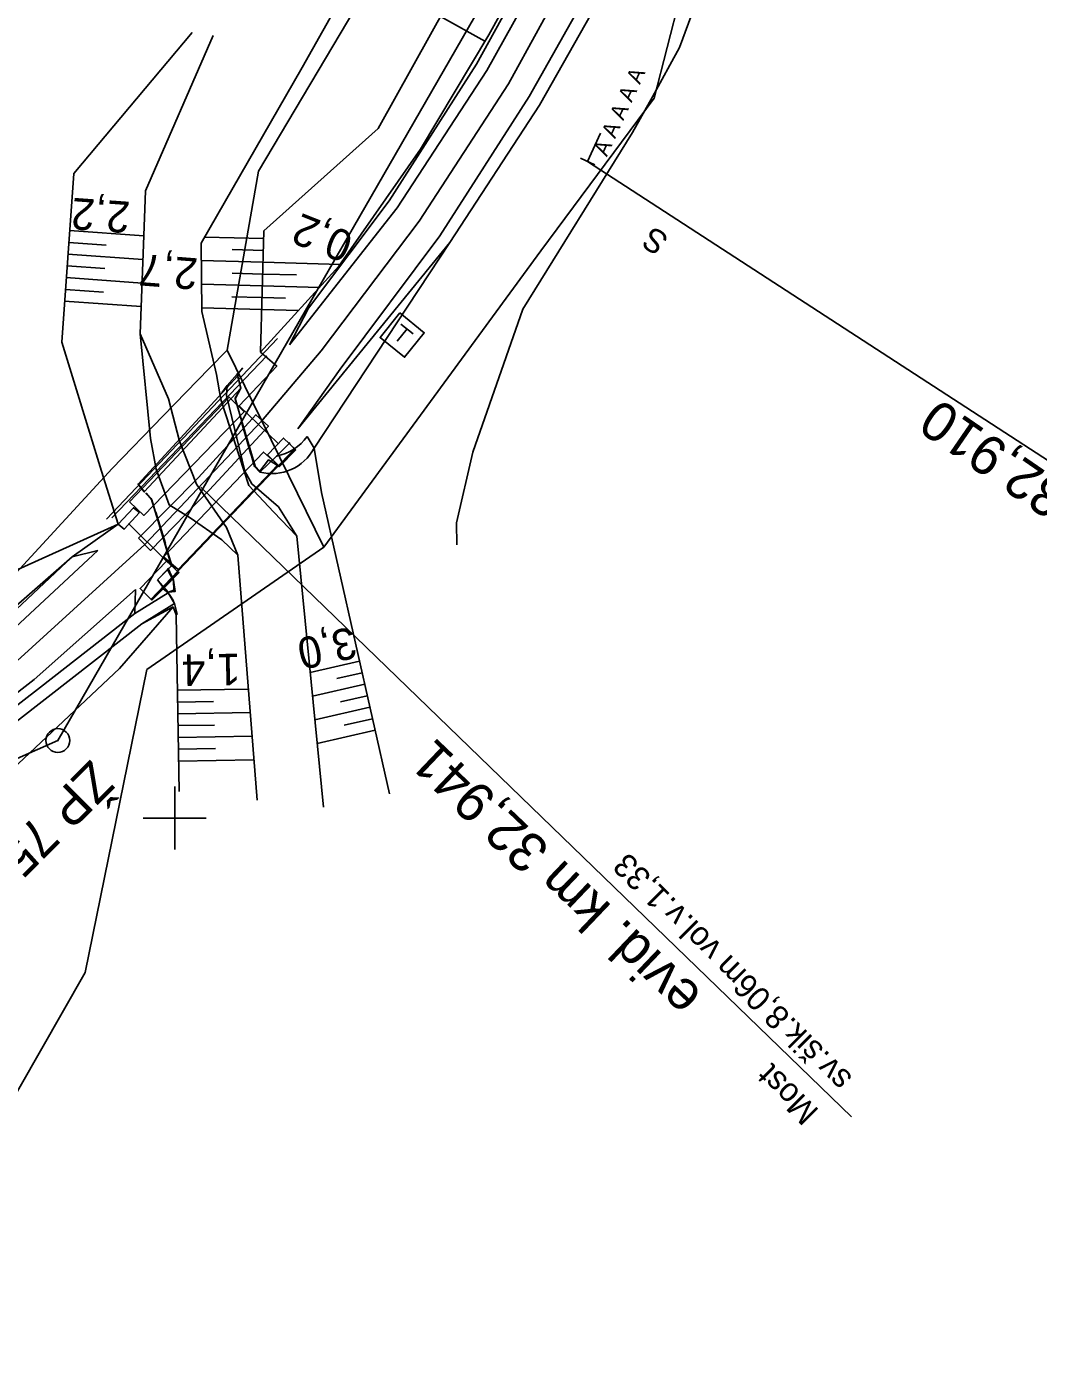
# Model space of a CAD drawing. Extents: x -804166 to -803706, y -1151030 to -1150147.
# Drawn here: x -803909.4 to -803845.1, y -1150734.2 to -1150649.7 of the extents above; entities that cross this region are included whole.
import ezdxf

# ---------------------------------------------------------------- set-up
doc = ezdxf.new("R2010")
doc.units = 0
for name, color, linetype in [('0381KM032-037P - Vrstva 1', 7, 'Continuous'), ('0381KM032-037P - Vrstva 13', 7, 'Continuous'), ('0381KM032-037P - Vrstva 17', 7, 'Continuous'), ('0381KM032-037P - Vrstva 18', 7, 'Continuous'), ('0381KM032-037P - Vrstva 33', 7, 'Continuous'), ('0381KM032-037P - Vrstva 35', 7, 'Continuous'), ('0381KM032-037P - Vrstva 4', 7, 'Continuous'), ('0381KM032-037P - Vrstva 48', 7, 'Continuous'), ('0381KM032-037P - Vrstva 49', 7, 'Continuous'), ('0381KM032-037P - Vrstva 50', 7, 'Continuous'), ('0381KM032-037P - Vrstva 55', 7, 'Continuous'), ('0381KM032-037P - Vrstva 6', 7, 'Continuous'), ('hran DP - hran DP', 7, 'Continuous'), ('krizky_1000 - Vrstva 1', 7, 'Continuous'), ('vyt_sit - polygon', 7, 'Continuous'), ('vyt_sit - stávající', 7, 'Continuous')]:
    doc.layers.add(name, color=color, linetype=linetype)

msp = doc.modelspace()

# ---------------------------------------------------------------- linework, layer by layer
at = {"layer": '0381KM032-037P - Vrstva 1'}
msp.add_line((-803894.474, -1150674.768), (-803901.906, -1150682.605), dxfattribs=at)
for points in [[(-803862.645, -1150536.71), (-803860.057, -1150547.81), (-803858.364, -1150558.718), (-803857.51, -1150569.546), (-803857.425, -1150579.975), (-803858.096, -1150590.725), (-803859.58, -1150601.687), (-803861.73, -1150611.946), (-803864.691, -1150622.329), (-803868.306, -1150632.261), (-803873.118, -1150643.006), (-803878.784, -1150653.323), (-803884.455, -1150662.043), (-803890.68, -1150670.289), (-803894.474, -1150674.768)], [(-803901.906, -1150682.605), (-803910.014, -1150690), (-803918.643, -1150696.775), (-803928.041, -1150703.062), (-803937.946, -1150708.688), (-803946.795, -1150712.932), (-803956.655, -1150716.869), (-803966.853, -1150720.098), (-803973.694, -1150721.813), (-803983.505, -1150723.682), (-803993.918, -1150724.91), (-804004.459, -1150725.421), (-804014.948, -1150725.206), (-804025.475, -1150724.252), (-804035.41, -1150722.673), (-804044.081, -1150720.735), (-804054.774, -1150717.615), (-804061.472, -1150715.138)]]:
    msp.add_lwpolyline(points, dxfattribs=at)
at = {"layer": '0381KM032-037P - Vrstva 13'}
for p, q in [((-803900.427, -1150685.689), (-803900.743, -1150685.422)), ((-803900.427, -1150685.69), (-803902.54, -1150686.99)), ((-803900.02, -1150686.371), (-803900.089, -1150686.205)), ((-803900.019, -1150686.37), (-803902.092, -1150687.65))]:
    msp.add_line(p, q, dxfattribs=at)
for points in [[(-803900.743, -1150685.422), (-803900.692, -1150685.394), (-803900.742, -1150685.419)], [(-803900.02, -1150686.371), (-803899.851, -1150687.044), (-803899.848, -1150687.042), (-803900.019, -1150686.37), (-803900.427, -1150685.69), (-803900.742, -1150685.419)], [(-803900.089, -1150686.205), (-803900.081, -1150686.195), (-803900.317, -1150685.837), (-803900.317, -1150685.836), (-803900.427, -1150685.689)], [(-803902.54, -1150686.99), (-803908.533, -1150691.682), (-803917.537, -1150698.646), (-803926.885, -1150705.063), (-803937.003, -1150710.487), (-803946.017, -1150714.661), (-803956.263, -1150718.85), (-803966.288, -1150722.189), (-803972.538, -1150724.259)], [(-803972.286, -1150725.012), (-803966.125, -1150722.974), (-803955.955, -1150719.581), (-803945.709, -1150715.376), (-803936.565, -1150711.19), (-803926.506, -1150705.78), (-803917.073, -1150699.315), (-803908.044, -1150692.29), (-803902.092, -1150687.65)]]:
    msp.add_lwpolyline(points, dxfattribs=at)
at = {"layer": '0381KM032-037P - Vrstva 17'}
for p, q in [((-803903.995, -1150680.91), (-803894.145, -1150670.618)), ((-803892.37, -1150676.505), (-803901.521, -1150686.105))]:
    msp.add_line(p, q, dxfattribs=at)
for points in [[(-803867.911, -1150651.01), (-803864.194, -1150640.965), (-803863.34, -1150639.848), (-803860.107, -1150635.351), (-803857.384, -1150629.008), (-803845.634, -1150598.77), (-803839.769, -1150573.178), (-803837.289, -1150572.72)], [(-803882.068, -1150682.623), (-803882.094, -1150681.238), (-803881.038, -1150676.732), (-803877.877, -1150667.643), (-803870.889, -1150656.426), (-803869.632, -1150654.159), (-803867.911, -1150651.01)]]:
    msp.add_lwpolyline(points, dxfattribs=at)
at = {"layer": '0381KM032-037P - Vrstva 18'}
for p, q in [((-803902.321, -1150678.769), (-803895.977, -1150671.88)), ((-803895.96, -1150671.875), (-803897.006, -1150672.976)), ((-803895.972, -1150671.746), (-803896.032, -1150671.776)), ((-803895.788, -1150672.67), (-803901.935, -1150679.269)), ((-803896.656, -1150672.511), (-803897.006, -1150672.976)), ((-803895.788, -1150672.67), (-803895.788, -1150672.67)), ((-803895.902, -1150673.797), (-803893.451, -1150676.167)), ((-803895.155, -1150676.86), (-803895.737, -1150674.89)), ((-803892.742, -1150676.15), (-803892.333, -1150676.585)), ((-803891.585, -1150675.741), (-803891.14, -1150676.484)), ((-803893.531, -1150676.988), (-803894.581, -1150678.003)), ((-803892.333, -1150676.585), (-803893.36, -1150677.66)), ((-803892.31, -1150676.591), (-803892.333, -1150676.585)), ((-803893.36, -1150677.66), (-803893.335, -1150677.645)), ((-803901.935, -1150679.269), (-803902.321, -1150678.769)), ((-803856.973, -1150719.009), (-803898.348, -1150678.956)), ((-803900.514, -1150683.661), (-803902.936, -1150681.284)), ((-803900.594, -1150682.547), (-803901.206, -1150680.55)), ((-803900.177, -1150683.94), (-803901.093, -1150684.85)), ((-803900.181, -1150683.948), (-803900.177, -1150683.94)), ((-803899.733, -1150684.407), (-803899.765, -1150684.362)), ((-803900.692, -1150685.394), (-803901.461, -1150686.142)), ((-803900.692, -1150685.394), (-803901.093, -1150684.85)), ((-803900.087, -1150684.927), (-803900.086, -1150684.886)), ((-803900.387, -1150685.649), (-803899.968, -1150685.591))]:
    msp.add_line(p, q, dxfattribs=at)
for points in [[(-803895.902, -1150673.797), (-803893.509, -1150671.262), (-803894.538, -1150670.386)], [(-803892.244, -1150682.081), (-803893.405, -1150680.212), (-803895.1, -1150678.76), (-803895.543, -1150677.939), (-803896.702, -1150673.136), (-803896.656, -1150672.511), (-803896.032, -1150671.776)], [(-803894.595, -1150677.949), (-803894.892, -1150677.628), (-803896.154, -1150673.353), (-803896.156, -1150673.313), (-803895.788, -1150672.67), (-803896.032, -1150671.776), (-803895.682, -1150671.402), (-803895.972, -1150671.746), (-803895.977, -1150671.88)], [(-803896.154, -1150673.353), (-803895.788, -1150672.67), (-803895.977, -1150671.88)], [(-803895.96, -1150671.875), (-803896.006, -1150671.732), (-803896.032, -1150671.776)], [(-803902.876, -1150679.904), (-803896.545, -1150673.237), (-803895.586, -1150674.167), (-803901.958, -1150680.766), (-803902.876, -1150679.904)], [(-803896.156, -1150673.313), (-803894.92, -1150677.658), (-803894.581, -1150678.003)], [(-803902.301, -1150682.211), (-803901.541, -1150682.984), (-803897.786, -1150679.126), (-803894.042, -1150675.093), (-803894.835, -1150674.357), (-803898.482, -1150678.342), (-803902.301, -1150682.211)], [(-803892.31, -1150676.591), (-803893.094, -1150675.842), (-803894.104, -1150676.91), (-803893.335, -1150677.645), (-803892.31, -1150676.591)], [(-803892.742, -1150676.15), (-803892.697, -1150676.16), (-803893.531, -1150676.988)], [(-803900.704, -1150683.386), (-803899.78, -1150684.198), (-803893.446, -1150677.55), (-803894.353, -1150676.739), (-803900.704, -1150683.386)], [(-803894.581, -1150678.003), (-803894.595, -1150677.949), (-803894.041, -1150677.229), (-803894.041, -1150677.229), (-803893.36, -1150677.66)], [(-803901.935, -1150679.269), (-803901.931, -1150679.271), (-803902.334, -1150678.769), (-803902.321, -1150678.769)], [(-803900.181, -1150683.948), (-803901.502, -1150679.684), (-803901.835, -1150679.365), (-803901.815, -1150679.357), (-803901.461, -1150679.762), (-803900.212, -1150683.983), (-803900.181, -1150683.948)], [(-803902.232, -1150680.579), (-803903.222, -1150681.645), (-803903.605, -1150681.318), (-803902.621, -1150680.279), (-803902.232, -1150680.579)], [(-803899.765, -1150684.362), (-803901.461, -1150686.142), (-803902.204, -1150685.415), (-803900.514, -1150683.661), (-803899.765, -1150684.362)], [(-803901.093, -1150684.85), (-803901.09, -1150684.852), (-803900.467, -1150684.209), (-803900.408, -1150684.126), (-803900.086, -1150684.886), (-803899.968, -1150685.591), (-803900.061, -1150685.507), (-803900.087, -1150684.927), (-803900.467, -1150684.209)], [(-803900.177, -1150683.94), (-803899.733, -1150684.407), (-803900.692, -1150685.394)], [(-803901.09, -1150684.852), (-803900.387, -1150685.649), (-803900.061, -1150685.507)]]:
    msp.add_lwpolyline(points, dxfattribs=at)
for centre, major_axis, ratio, start_param, end_param in [((-803893.838, -1150674.452), (2.475, 1.269), 0.908828, 4.38934, 5.247205), ((-803893.887, -1150674.932), (1.395, -2.862), 0.971802, 5.593201, 6.899505)]:
    msp.add_ellipse(centre, major_axis=major_axis, ratio=ratio, start_param=start_param, end_param=end_param, dxfattribs=at)
at = {"layer": '0381KM032-037P - Vrstva 33'}
for p, q in [((-803885.617, -1150668.595), (-803884.838, -1150669.222)), ((-803885.227, -1150668.909), (-803885.855, -1150669.687))]:
    msp.add_line(p, q, dxfattribs=at)
msp.add_lwpolyline([(-803885.693, -1150667.892), (-803884.135, -1150669.146), (-803885.389, -1150670.704), (-803886.947, -1150669.45), (-803885.693, -1150667.892)], dxfattribs=at)
at = {"layer": '0381KM032-037P - Vrstva 35'}
msp.add_line((-803904.333, -1150681.001), (-803893.471, -1150669.506), dxfattribs=at)
at = {"layer": '0381KM032-037P - Vrstva 4'}
for points in [[(-803862.041, -1150601.171), (-803863.934, -1150611.478), (-803866.955, -1150621.666), (-803870.636, -1150631.623), (-803875.322, -1150642.112), (-803880.813, -1150652.073), (-803886.36, -1150660.761), (-803891.5, -1150667.581), (-803892.695, -1150669.921)], [(-803861.107, -1150601.386), (-803863.249, -1150611.592), (-803866.278, -1150621.841), (-803869.683, -1150631.826), (-803874.548, -1150642.393), (-803880.159, -1150652.477), (-803885.847, -1150661.208), (-803892.695, -1150669.921)], [(-803858.016, -1150602.009), (-803860.157, -1150612.315), (-803863.229, -1150623.106), (-803866.722, -1150632.775), (-803871.621, -1150643.742), (-803877.472, -1150654.13), (-803883.137, -1150662.978), (-803889.477, -1150671.458), (-803892.178, -1150675.246)], [(-803857.109, -1150602.102), (-803859.611, -1150612.518), (-803862.49, -1150623.34), (-803866.1, -1150633.182), (-803870.873, -1150644.181), (-803876.806, -1150654.687), (-803882.51, -1150663.405), (-803892.178, -1150675.246)], [(-803904.886, -1150683.001), (-803906.516, -1150683.391), (-803911.518, -1150688.069), (-803920.109, -1150694.835), (-803929.412, -1150700.935), (-803939.155, -1150706.209), (-803947.889, -1150710.398), (-803957.601, -1150714.533), (-803967.413, -1150717.637)], [(-803904.886, -1150683.001), (-803911.05, -1150688.735), (-803919.705, -1150695.384), (-803929.087, -1150701.477), (-803938.787, -1150707.105), (-803947.481, -1150711.337), (-803957.418, -1150715.321), (-803967.176, -1150718.433)], [(-803902.503, -1150685.469), (-803908.943, -1150691.185), (-803917.694, -1150697.991), (-803927.241, -1150704.348), (-803937.195, -1150710.055), (-803946.246, -1150714.302), (-803956.405, -1150718.419), (-803966.448, -1150721.526)], [(-803902.503, -1150685.469), (-803902.54, -1150686.99), (-803908.533, -1150691.682), (-803917.537, -1150698.646), (-803926.885, -1150705.063), (-803937.003, -1150710.487), (-803946.017, -1150714.661), (-803956.263, -1150718.85), (-803966.288, -1150722.189)]]:
    msp.add_lwpolyline(points, dxfattribs=at)
at = {"layer": '0381KM032-037P - Vrstva 48'}
for p, q in [((-803883.093, -1150649.037), (-803880.278, -1150650.604)), ((-803906.68, -1150662.653), (-803901.962, -1150662.988)), ((-803906.733, -1150663.401), (-803904.362, -1150663.569)), ((-803894.338, -1150663.165), (-803898.097, -1150663.061)), ((-803906.786, -1150664.149), (-803902.02, -1150664.487)), ((-803894.358, -1150663.915), (-803896.337, -1150663.86)), ((-803906.84, -1150664.897), (-803904.445, -1150665.067)), ((-803894.379, -1150664.664), (-803898.309, -1150664.555)), ((-803894.379, -1150664.664), (-803889.482, -1150664.8)), ((-803906.893, -1150665.645), (-803902.079, -1150665.987)), ((-803894.421, -1150666.164), (-803898.295, -1150666.056)), ((-803894.4, -1150665.414), (-803896.351, -1150665.36)), ((-803894.4, -1150665.414), (-803892.261, -1150665.473)), ((-803906.946, -1150666.394), (-803904.527, -1150666.565)), ((-803894.442, -1150666.913), (-803896.365, -1150666.86)), ((-803894.442, -1150666.913), (-803892.948, -1150666.955)), ((-803894.421, -1150666.164), (-803890.788, -1150666.265)), ((-803906.999, -1150667.142), (-803902.138, -1150667.487)), ((-803894.462, -1150667.663), (-803898.28, -1150667.557)), ((-803894.462, -1150667.663), (-803892.12, -1150667.728)), ((-803888.25, -1150690.03), (-803891.388, -1150690.739)), ((-803888.085, -1150690.761), (-803889.7, -1150691.126)), ((-803899.836, -1150691.878), (-803895.322, -1150691.802)), ((-803887.92, -1150691.493), (-803891.24, -1150692.243)), ((-803887.754, -1150692.224), (-803889.46, -1150692.61)), ((-803899.823, -1150692.628), (-803897.543, -1150692.589)), ((-803887.589, -1150692.956), (-803891.092, -1150693.748)), ((-803899.81, -1150693.378), (-803895.204, -1150693.3)), ((-803887.424, -1150693.688), (-803889.221, -1150694.094)), ((-803899.798, -1150694.128), (-803897.472, -1150694.088)), ((-803899.785, -1150694.878), (-803895.086, -1150694.798)), ((-803887.258, -1150694.419), (-803890.945, -1150695.252)), ((-803899.772, -1150695.628), (-803897.4, -1150695.587)), ((-803899.76, -1150696.377), (-803894.968, -1150696.296))]:
    msp.add_line(p, q, dxfattribs=at)
at = {"layer": '0381KM032-037P - Vrstva 49'}
for p, q in [((-803882.51, -1150663.405), (-803891.14, -1150676.484)), ((-803900.099, -1150686.57), (-803902.092, -1150687.65))]:
    msp.add_line(p, q, dxfattribs=at)
for points in [[(-803855.009, -1150569.422), (-803855.013, -1150580.14), (-803855.681, -1150591.137), (-803857.109, -1150602.102), (-803859.611, -1150612.518), (-803862.49, -1150623.34), (-803866.1, -1150633.182), (-803870.873, -1150644.181), (-803876.806, -1150654.687), (-803882.51, -1150663.405)], [(-803867.826, -1150615.469), (-803873.958, -1150632.621), (-803887.064, -1150656.172), (-803894.324, -1150662.675), (-803894.538, -1150670.386)], [(-803865.684, -1150616.069), (-803868.473, -1150625.045), (-803871.506, -1150633.468), (-803875.458, -1150641.91), (-803880.036, -1150650.199), (-803884.384, -1150657.469), (-803889.567, -1150664.922), (-803894.538, -1150670.386)], [(-803879.144, -1150629.624), (-803891.889, -1150652.288), (-803898.32, -1150663.448), (-803898.278, -1150667.796), (-803897.353, -1150671.802), (-803897.063, -1150673.395), (-803895.285, -1150678.85), (-803893.718, -1150680.524), (-803892.244, -1150682.081)], [(-803857.384, -1150629.008), (-803860.107, -1150635.351), (-803863.34, -1150639.848), (-803864.194, -1150640.965), (-803867.911, -1150651.01), (-803869.632, -1150654.159), (-803870.889, -1150656.426), (-803877.877, -1150667.643), (-803881.038, -1150676.732), (-803882.094, -1150681.238), (-803882.068, -1150682.623)], [(-803903.605, -1150681.318), (-803904.65, -1150677.954), (-803907.183, -1150669.738), (-803906.423, -1150659.026), (-803898.899, -1150650.067)], [(-803902.205, -1150669.209), (-803901.85, -1150660.131), (-803897.556, -1150650.259)], [(-803882.094, -1150681.238), (-803881.038, -1150676.732), (-803877.877, -1150667.643), (-803870.889, -1150656.426), (-803869.632, -1150654.159), (-803867.911, -1150651.01)], [(-803895.993, -1150683.294), (-803896.707, -1150681.538), (-803898.609, -1150678.776), (-803899.692, -1150676.05), (-803900.386, -1150673.352), (-803902.205, -1150669.209)], [(-803895.993, -1150683.294), (-803897.012, -1150682.314), (-803899.014, -1150680.911), (-803900.346, -1150680.09), (-803901.19, -1150677.817), (-803901.54, -1150675.88), (-803902.205, -1150669.209)], [(-803886.343, -1150698.471), (-803890.675, -1150679.297), (-803891.14, -1150676.484)], [(-803984.817, -1150721.442), (-803974.636, -1150719.233), (-803973.09, -1150718.927), (-803972.805, -1150718.807), (-803972.246, -1150718.741), (-803965.21, -1150716.746), (-803957.601, -1150714.533), (-803947.889, -1150710.398), (-803939.155, -1150706.209), (-803931.831, -1150702.119), (-803924.086, -1150697.218), (-803916.608, -1150691.841), (-803910.081, -1150686.51), (-803906.516, -1150683.391), (-803903.605, -1150681.318)], [(-803972.246, -1150718.741), (-803965.841, -1150714.337), (-803956.596, -1150711.219), (-803948.841, -1150707.727), (-803941.393, -1150704.085), (-803932.776, -1150700.061), (-803925.787, -1150694.954), (-803918.146, -1150689.679), (-803911.549, -1150684.903), (-803903.605, -1150681.318)], [(-803890.546, -1150699.304), (-803892.24, -1150682.08)], [(-803894.766, -1150698.862), (-803895.993, -1150683.294)], [(-803973.24, -1150730.36), (-803966.718, -1150727.463), (-803955.163, -1150723.59), (-803942.536, -1150718.416), (-803927.909, -1150711.458), (-803917.773, -1150704.055), (-803910.649, -1150697.212), (-803903.52, -1150690.487), (-803900.099, -1150686.57)], [(-803900.099, -1150686.57), (-803899.917, -1150687.085), (-803899.727, -1150698.309)], [(-803902.092, -1150687.65), (-803908.044, -1150692.29), (-803917.073, -1150699.315), (-803926.506, -1150705.78), (-803936.565, -1150711.19), (-803945.709, -1150715.376), (-803955.955, -1150719.581), (-803966.125, -1150722.974), (-803972.286, -1150725.012), (-803974.7, -1150725.768), (-803983.368, -1150727.37), (-803993.836, -1150727.905), (-804004.989, -1150728.615), (-804004.868, -1150729.928), (-804012.985, -1150730.258), (-804018.762, -1150729.808), (-804029.792, -1150728.642), (-804054.152, -1150723.147), (-804060.274, -1150720.943)]]:
    msp.add_lwpolyline(points, dxfattribs=at)
at = {"layer": '0381KM032-037P - Vrstva 50'}
for points in [[(-803870.937, -1150611.902), (-803879.144, -1150629.624), (-803891.889, -1150652.288), (-803898.32, -1150663.448), (-803898.278, -1150667.796), (-803897.353, -1150671.802), (-803897.063, -1150673.395)], [(-803900.386, -1150673.352), (-803902.205, -1150669.209), (-803901.85, -1150660.131), (-803897.556, -1150650.259)], [(-803900.386, -1150673.352), (-803899.692, -1150676.05), (-803898.609, -1150678.776), (-803896.707, -1150681.538), (-803895.993, -1150683.294)], [(-803892.24, -1150682.08), (-803893.718, -1150680.524), (-803895.285, -1150678.85), (-803897.063, -1150673.395)], [(-803890.546, -1150699.304), (-803892.244, -1150682.081)], [(-803894.766, -1150698.862), (-803895.993, -1150683.294)]]:
    msp.add_lwpolyline(points, dxfattribs=at)
at = {"layer": '0381KM032-037P - Vrstva 55'}
msp.add_line((-803896.67, -1150670.26), (-803890.53, -1150682.77), dxfattribs=at)
at = {"layer": '0381KM032-037P - Vrstva 6'}
for p, q in [((-803872.924, -1150656.457), (-803873.746, -1150658.258)), ((-803874.201, -1150658.05), (-803873.291, -1150658.466)), ((-803873.746, -1150658.258), (-803837.626, -1150681.738))]:
    msp.add_line(p, q, dxfattribs=at)
at = {"layer": 'hran DP - hran DP'}
for p, q in [((-803894.67, -1150658.87), (-803877.2, -1150629.46)), ((-803866.11, -1150640.84), (-803869.51, -1150654.24)), ((-803869.51, -1150654.24), (-803876.72, -1150663.94)), ((-803896.67, -1150670.26), (-803894.67, -1150658.87)), ((-803876.72, -1150663.94), (-803890.53, -1150682.77)), ((-803897.8, -1150671.42), (-803896.67, -1150670.26)), ((-803900.74, -1150674.44), (-803897.8, -1150671.42)), ((-803903.98, -1150677.77), (-803900.74, -1150674.44)), ((-803907.67, -1150681.78), (-803903.98, -1150677.77)), ((-803914.58, -1150689.29), (-803907.67, -1150681.78)), ((-803890.53, -1150682.77), (-803901.78, -1150690.55)), ((-803901.78, -1150690.55), (-803905.7, -1150709.82)), ((-803905.7, -1150709.82), (-803919.68, -1150734.23))]:
    msp.add_line(p, q, dxfattribs=at)
at = {"layer": 'krizky_1000 - Vrstva 1'}
for points in [[(-803900, -1150698), (-803900, -1150702)], [(-803902, -1150700), (-803898, -1150700)]]:
    msp.add_lwpolyline(points, dxfattribs=at)
at = {"layer": 'vyt_sit - polygon'}
for p, q in [((-803907.43, -1150695.075), (-803857.351, -1150608.078)), ((-803975.818, -1150725.31), (-803907.43, -1150695.075))]:
    msp.add_line(p, q, dxfattribs=at)
at = {"layer": 'vyt_sit - stávající'}
msp.add_line((-803907.48, -1150695.075), (-803907.38, -1150695.075), dxfattribs=at)
msp.add_circle((-803907.43, -1150695.075), 0.756, dxfattribs=at)

# ---------------------------------------------------------------- texts
at = {"layer": '0381KM032-037P - Vrstva 18'}
for s, height, rotation, p in [('evid. km 32,941', 2.5, 136.38556, (-803866.362, -1150711.135)), ('sv.šik.8,06m vol.v.1,33', 1.5, 134.97726, (-803856.852, -1150716.475)), ('Most', 1.5, 134.97726, (-803858.974, -1150718.595))]:
    msp.add_text(s, height=height, rotation=rotation, dxfattribs=at).set_placement(p)
at = {"layer": '0381KM032-037P - Vrstva 48'}
for s, rotation, p in [('2,2', 175.94175, (-803902.788, -1150660.827)), ('0,2', 158.4103, (-803888.52, -1150662.876)), ('2,7', 175.55344, (-803898.475, -1150664.424)), ('3,0', 192.73114, (-803888.718, -1150687.818)), ('1,4', 180.96981, (-803895.839, -1150689.546))]:
    msp.add_text(s, height=2, rotation=rotation, dxfattribs=at).set_placement(p)
at = {"layer": '0381KM032-037P - Vrstva 6'}
for s, height, rotation, p in [('  A A A A A ', 1, 65.47944, (-803872.836, -1150658.673)), ('S', 1.5, 146.15257, (-803868.497, -1150663.067)), ('km 32,910', 2.5, 145.47944, (-803838.584, -1150682.1))]:
    msp.add_text(s, height=height, rotation=rotation, dxfattribs=at).set_placement(p)
at = {"layer": 'vyt_sit - stávající'}
msp.add_text('ŽP 758', height=2.4, rotation=225, dxfattribs=at).set_placement((-803905.333, -1150696.219))

doc.saveas('drawing.dxf')
